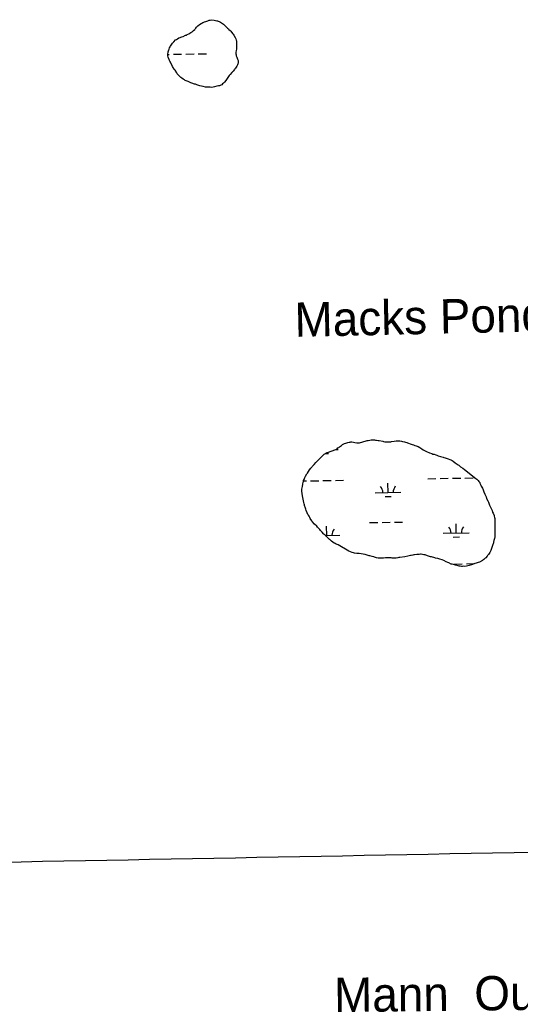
# Model space of a CAD drawing. Extents: x 3957609 to 3995875, y 234277 to 260273.
# Drawn here: x 3968015 to 3969955, y 248323 to 252171 of the extents above; entities that cross this region are included whole.
import ezdxf

# ---------------------------------------------------------------- set-up
doc = ezdxf.new("R2010")
doc.units = 0
for name, color, linetype in [('V-GRID-MAJR', 7, 'Continuous'), ('V-RIVR-IDEN', 7, 'Continuous'), ('V-TOPO-SHOR', 7, 'Continuous'), ('V-WETL-SWMP', 7, 'Continuous')]:
    doc.layers.add(name, color=color, linetype=linetype)

msp = doc.modelspace()

# ---------------------------------------------------------------- linework, layer by layer
at = {"layer": 'V-GRID-MAJR'}
msp.add_spline([(3961703.892, 248787.859), (3967022.571, 248887.277), (3972341.236, 248987.469), (3977659.886, 249088.434), (3982978.522, 249190.173), (3988297.143, 249292.685), (3993615.748, 249395.971), (3993615.749, 249395.971)], degree=3, dxfattribs=at)
at = {"layer": 'V-TOPO-SHOR'}
for points in [[(3968590.487, 252047.006), (3968591.671, 252050.578), (3968593.252, 252053.753), (3968594.438, 252056.927), (3968596.015, 252062.086), (3968597.596, 252065.658), (3968599.572, 252068.437), (3968603.922, 252075.977), (3968607.088, 252080.346), (3968609.464, 252082.728), (3968611.84, 252085.509), (3968618.967, 252092.656), (3968622.135, 252094.645), (3968626.096, 252097.426), (3968631.644, 252100.609), (3968636.397, 252102.599), (3968639.965, 252103.795), (3968643.137, 252104.592), (3968647.893, 252106.187), (3968657.801, 252110.564), (3968661.366, 252111.76), (3968664.535, 252114.146), (3968670.478, 252116.929), (3968678.008, 252120.909), (3968683.157, 252124.486), (3968685.928, 252127.266), (3968689.096, 252129.649), (3968693.055, 252133.623), (3968695.036, 252136.402), (3968697.409, 252138.786), (3968700.575, 252142.755), (3968702.951, 252144.741), (3968705.327, 252147.522), (3968711.663, 252152.687), (3968718.002, 252157.06), (3968720.777, 252158.254), (3968725.135, 252159.847), (3968727.908, 252161.834), (3968731.078, 252162.632), (3968736.231, 252164.623), (3968739.799, 252165.819), (3968743.764, 252166.62), (3968749.312, 252169.008), (3968752.482, 252169.805), (3968759.619, 252170.609), (3968768.344, 252169.831), (3968773.898, 252168.649), (3968778.659, 252167.07), (3968781.834, 252166.284), (3968784.611, 252165.098), (3968788.183, 252163.914), (3968792.944, 252161.543), (3968796.516, 252159.169), (3968800.487, 252156.003), (3968804.458, 252153.232), (3968806.842, 252150.858), (3968810.414, 252148.485), (3968820.344, 252138.587), (3968823.521, 252136.211), (3968825.905, 252133.44), (3968830.67, 252128.689), (3968833.45, 252126.313), (3968840.206, 252117.996), (3968842.193, 252114.828), (3968844.976, 252111.262), (3968849.75, 252101.754), (3968852.138, 252096.603), (3968853.731, 252091.845), (3968854.53, 252088.675), (3968855.73, 252081.54), (3968855.74, 252075.193), (3968855.353, 252070.038), (3968855.357, 252066.469), (3968854.573, 252061.312), (3968854.579, 252057.742), (3968853.399, 252050.603), (3968853.012, 252045.448), (3968853.022, 252039.103), (3968853.426, 252035.534), (3968854.227, 252030.776), (3968856.215, 252026.418), (3968859.005, 252018.49), (3968861.393, 252012.942), (3968862.191, 252009.374), (3968862.195, 252006.202), (3968861.806, 252002.632), (3968860.62, 251999.458), (3968859.039, 251995.886), (3968856.67, 251991.125), (3968851.525, 251983.185), (3968849.152, 251980.405), (3968847.173, 251977.626), (3968842.027, 251971.671), (3968836.88, 251966.108), (3968830.152, 251958.166), (3968826.986, 251954.197), (3968823.82, 251950.623), (3968821.842, 251947.447), (3968818.675, 251943.476), (3968814.325, 251935.935), (3968808.786, 251929.185)], [(3968808.786, 251929.185), (3968804.827, 251925.212), (3968801.261, 251922.033), (3968797.698, 251919.252), (3968794.132, 251916.866), (3968789.774, 251915.275), (3968785.014, 251914.472), (3968779.466, 251912.879), (3968769.556, 251910.483), (3968760.041, 251908.881), (3968753.299, 251909.266), (3968750.127, 251909.657), (3968744.575, 251909.254), (3968735.056, 251910.03), (3968725.536, 251911.601), (3968713.236, 251915.15), (3968709.666, 251915.939), (3968705.697, 251917.518), (3968701.333, 251918.699), (3968696.176, 251920.676), (3968692.605, 251921.462), (3968681.894, 251925.013), (3968678.717, 251926.594), (3968675.147, 251927.778), (3968667.209, 251930.938), (3968659.671, 251934.495), (3968656.496, 251935.679), (3968653.715, 251937.658), (3968648.556, 251940.426), (3968642.998, 251944.383), (3968639.424, 251947.152), (3968635.85, 251951.113), (3968631.482, 251954.674), (3968625.522, 251961.803), (3968623.534, 251964.576), (3968616.775, 251975.271), (3968613.597, 251979.629), (3968607.234, 251990.326), (3968605.247, 251993.099), (3968600.871, 252002.213), (3968598.88, 252006.968), (3968596.891, 252009.741), (3968595.697, 252012.911), (3968593.709, 252016.477), (3968592.515, 252019.252), (3968590.522, 252025.99), (3968588.529, 252031.538), (3968588.521, 252035.9), (3968590.487, 252047.006)], [(3969108.75, 250350.965), (3969110.714, 250361.279), (3969111.892, 250370.006), (3969113.464, 250377.542), (3969114.65, 250380.717), (3969115.439, 250383.889), (3969117.413, 250388.653), (3969118.597, 250392.222), (3969120.178, 250395.399), (3969122.152, 250400.556), (3969127.69, 250410.083), (3969130.064, 250413.259), (3969138.768, 250425.963), (3969143.515, 250432.316), (3969146.683, 250435.493), (3969148.659, 250439.066), (3969156.182, 250446.611), (3969162.911, 250454.158), (3969172.019, 250463.292), (3969173.997, 250465.676), (3969177.165, 250468.457), (3969191.022, 250482.359), (3969195.378, 250486.332), (3969206.075, 250492.298), (3969211.228, 250494.686), (3969222.721, 250498.274), (3969239.763, 250504.645), (3969244.913, 250507.429), (3969248.479, 250510.607), (3969251.647, 250512.198), (3969254.815, 250514.98), (3969261.944, 250520.147), (3969265.905, 250523.325), (3969268.678, 250525.314), (3969273.829, 250527.7), (3969278.584, 250529.69), (3969286.91, 250532.084), (3969292.46, 250533.283), (3969295.632, 250533.287), (3969298.804, 250533.688), (3969302.769, 250533.696), (3969308.321, 250533.307), (3969313.478, 250531.73), (3969321.412, 250530.95), (3969332.119, 250530.966), (3969344.805, 250533.764), (3969358.28, 250537.751), (3969361.453, 250538.945), (3969365.018, 250539.744), (3969372.156, 250540.549), (3969376.913, 250541.747), (3969382.068, 250542.15), (3969389.602, 250541.767), (3969393.967, 250540.981), (3969397.932, 250540.987), (3969404.676, 250539.412), (3969408.643, 250539.021), (3969422.526, 250536.269), (3969425.698, 250535.877), (3969430.857, 250534.696), (3969437.202, 250533.911), (3969444.737, 250533.924), (3969453.064, 250534.73), (3969456.631, 250535.529), (3969466.146, 250537.131), (3969473.681, 250537.54), (3969476.853, 250537.544), (3969481.611, 250537.95), (3969484.783, 250537.559), (3969488.353, 250537.565), (3969494.304, 250536.383), (3969498.269, 250535.994), (3969506.203, 250534.024), (3969510.965, 250532.445), (3969515.329, 250531.261), (3969518.106, 250530.077), (3969532.391, 250525.738), (3969535.963, 250524.159), (3969541.12, 250522.58), (3969543.899, 250521.394), (3969547.071, 250520.605), (3969552.23, 250518.236), (3969555.404, 250517.447), (3969558.976, 250515.866), (3969565.724, 250511.912), (3969569.296, 250510.333), (3969573.265, 250507.166), (3969579.221, 250503.607), (3969591.525, 250496.883), (3969603.035, 250491.352), (3969612.159, 250488.589), (3969616.525, 250487.01), (3969621.285, 250485.828), (3969627.633, 250483.461), (3969632.395, 250482.277), (3969636.759, 250480.303), (3969645.488, 250477.937), (3969651.439, 250475.568), (3969655.804, 250474.781), (3969659.373, 250473.598), (3969664.532, 250471.621)], [(3969664.532, 250471.621), (3969672.071, 250469.651), (3969676.038, 250468.072), (3969681.991, 250465.305), (3969685.561, 250464.519), (3969688.338, 250463.333), (3969691.515, 250461.752), (3969694.691, 250459.774), (3969703.028, 250453.046), (3969706.207, 250450.275), (3969710.176, 250447.901), (3969714.145, 250445.133), (3969716.924, 250443.551), (3969719.306, 250441.571), (3969721.292, 250439.593), (3969723.279, 250437.217), (3969733.202, 250431.679), (3969739.554, 250426.932), (3969783.629, 250391.708), (3969786.806, 250389.335), (3969791.572, 250384.981), (3969795.147, 250381.022), (3969797.929, 250377.059), (3969798.727, 250373.889), (3969800.319, 250371.116), (3969802.707, 250365.963), (3969804.3, 250362), (3969808.275, 250354.869), (3969811.062, 250348.528), (3969813.051, 250344.565), (3969814.247, 250340.603), (3969818.228, 250331.092), (3969822.607, 250321.581), (3969824.995, 250314.448), (3969828.976, 250305.332), (3969831.762, 250300.181), (3969836.538, 250288.69), (3969842.507, 250275.214), (3969846.487, 250267.688), (3969848.08, 250262.138), (3969850.468, 250258.177), (3969853.655, 250249.059), (3969854.453, 250245.491), (3969856.049, 250240.341), (3969856.845, 250237.168), (3969856.852, 250233.601), (3969857.253, 250230.031), (3969857.3, 250201.48), (3969856.913, 250195.53), (3969856.923, 250189.186), (3969856.536, 250183.632), (3969856.542, 250179.269), (3969856.944, 250176.097), (3969856.559, 250169.355), (3969856.565, 250166.185), (3969855.385, 250159.441), (3969854.202, 250155.076), (3969853.415, 250151.109), (3969851.443, 250145.553), (3969851.05, 250142.381), (3969847.498, 250132.065), (3969845.917, 250128.891), (3969844.734, 250124.526), (3969840.785, 250113.416), (3969836.834, 250104.685), (3969832.087, 250097.143), (3969828.921, 250093.569), (3969826.943, 250090.79), (3969821.798, 250084.834), (3969819.025, 250082.845), (3969813.481, 250077.68), (3969810.708, 250075.694), (3969808.332, 250073.707), (3969797.238, 250067.741), (3969792.086, 250065.751), (3969787.725, 250064.553), (3969784.952, 250063.359), (3969779.8, 250062.161), (3969775.835, 250060.965), (3969769.494, 250058.575), (3969765.927, 250057.778), (3969757.603, 250054.986), (3969746.503, 250052.193), (3969738.573, 250051.386), (3969733.814, 250051.775), (3969730.246, 250050.979), (3969727.074, 250050.972), (3969722.314, 250051.759), (3969718.745, 250052.545), (3969714.776, 250053.729), (3969704.067, 250055.693), (3969699.702, 250056.877), (3969690.974, 250060.035), (3969687.007, 250060.426), (3969677.879, 250064.774), (3969674.307, 250065.958), (3969667.956, 250069.515), (3969658.431, 250074.258), (3969652.48, 250076.63), (3969642.956, 250079.786), (3969636.212, 250081.758)], [(3969636.212, 250081.758), (3969627.089, 250083.726), (3969623.914, 250084.91), (3969620.344, 250085.301), (3969615.188, 250086.483), (3969611.219, 250088.062), (3969607.649, 250088.453), (3969598.92, 250091.216), (3969595.748, 250092.002), (3969586.223, 250095.557), (3969581.861, 250096.344), (3969575.909, 250097.919), (3969571.547, 250098.705), (3969567.975, 250098.699), (3969563.617, 250097.9), (3969557.667, 250097.89), (3969554.1, 250097.489), (3969545.775, 250095.492), (3969542.602, 250095.486), (3969538.242, 250094.29), (3969532.69, 250093.487), (3969529.52, 250093.483), (3969518.817, 250090.689), (3969507.319, 250088.291), (3969488.287, 250086.278), (3969484.72, 250085.479), (3969480.755, 250085.076), (3969473.62, 250083.083), (3969458.948, 250083.058), (3969454.188, 250083.843), (3969450.221, 250083.837), (3969447.049, 250084.625), (3969441.497, 250085.012), (3969433.168, 250085), (3969425.24, 250083.798), (3969421.273, 250083.79), (3969417.31, 250082.991), (3969412.153, 250082.983), (3969408.188, 250082.579), (3969403.826, 250082.968), (3969398.272, 250084.15), (3969393.907, 250085.729), (3969390.735, 250086.517), (3969387.956, 250087.701), (3969380.814, 250089.276), (3969372.483, 250091.644), (3969369.309, 250092.827), (3969365.739, 250093.616), (3969353.441, 250097.163), (3969337.968, 250099.915), (3969331.226, 250100.698), (3969326.862, 250101.482), (3969322.104, 250101.871), (3969312.583, 250103.047), (3969308.616, 250104.231), (3969303.064, 250105.015), (3969290.367, 250110.149), (3969249.083, 250135.065), (3969241.147, 250137.828), (3969237.973, 250139.806), (3969234.401, 250141.783), (3969223.68, 250149.301), (3969218.914, 250154.052), (3969216.135, 250156.031), (3969213.753, 250158.406), (3969206.603, 250164.344), (3969203.822, 250167.512), (3969198.661, 250171.864), (3969195.483, 250175.032), (3969192.306, 250177.803), (3969186.744, 250184.139), (3969181.182, 250190.871), (3969178.003, 250194.037), (3969172.043, 250201.167), (3969169.264, 250203.542), (3969166.88, 250206.711), (3969158.142, 250215.421), (3969149.003, 250225.718), (3969146.62, 250228.092), (3969140.658, 250237.203), (3969139.064, 250240.771), (3969136.281, 250246.317), (3969134.293, 250249.882), (3969132.304, 250252.655), (3969129.519, 250258.601), (3969125.539, 250267.714), (3969123.944, 250273.262), (3969122.351, 250277.225), (3969119.162, 250287.135), (3969118.363, 250290.308), (3969117.169, 250293.476), (3969115.574, 250299.026), (3969110.773, 250324.794), (3969109.966, 250334.311), (3969108.365, 250343.431), (3969108.359, 250346.999), (3969108.75, 250350.965)]]:
    msp.add_lwpolyline(points, dxfattribs=at)
at = {"layer": 'V-WETL-SWMP'}
for p, q in [((3968588.656, 252036.655), (3968594.454, 252036.761)), ((3968610.452, 252037.052), (3968642.446, 252037.633)), ((3968658.444, 252037.924), (3968690.438, 252038.506)), ((3968706.436, 252038.797), (3968738.431, 252039.379)), ((3969240.319, 250504.945), (3969249.16, 250505.106)), ((3969199.758, 250488.774), (3969211.447, 250488.987)), ((3969115.112, 250382.578), (3969126.52, 250382.785)), ((3969142.517, 250383.076), (3969174.512, 250383.658)), ((3969190.509, 250383.949), (3969222.504, 250384.531)), ((3969238.501, 250384.822), (3969270.496, 250385.403)), ((3969596.35, 250391.328), (3969628.345, 250391.91)), ((3969644.342, 250392.201), (3969676.337, 250392.783)), ((3969692.334, 250393.074), (3969724.329, 250393.655)), ((3969740.326, 250393.946), (3969772.321, 250394.528)), ((3969442.706, 250337.784), (3969442.052, 250373.778)), ((3969392.714, 250336.875), (3969492.698, 250338.693)), ((3969430.989, 250322.138), (3969454.985, 250322.574)), ((3969205.216, 250171.577), (3969204.562, 250207.571)), ((3969371.409, 250221.037), (3969403.403, 250221.619)), ((3969419.401, 250221.909), (3969451.396, 250222.491)), ((3969467.393, 250222.782), (3969499.388, 250223.364)), ((3969707.042, 250180.702), (3969706.387, 250216.696)), ((3969199.132, 250171.467), (3969255.208, 250172.486)), ((3969215.827, 250156.337), (3969217.495, 250156.367)), ((3969657.05, 250179.793), (3969757.033, 250181.611)), ((3969695.324, 250165.055), (3969719.32, 250165.492)), ((3969698.382, 250060.454), (3969730.377, 250061.035)), ((3969746.374, 250061.326), (3969778.369, 250061.908))]:
    msp.add_line(p, q, dxfattribs=at)
for points in [[(3968590.487, 252047.007), (3968591.671, 252050.578), (3968593.252, 252053.753), (3968594.437, 252056.927), (3968596.015, 252062.085), (3968597.595, 252065.657), (3968599.573, 252068.436), (3968603.923, 252075.977), (3968607.089, 252080.345), (3968609.464, 252082.728), (3968611.839, 252085.508), (3968618.966, 252092.657), (3968622.135, 252094.645), (3968626.096, 252097.427), (3968631.643, 252100.609), (3968636.398, 252102.599), (3968639.965, 252103.795), (3968643.137, 252104.593), (3968647.893, 252106.187), (3968657.8, 252110.565), (3968661.367, 252111.76), (3968664.535, 252114.145), (3968670.479, 252116.93), (3968678.008, 252120.908), (3968683.157, 252124.486), (3968685.929, 252127.266), (3968689.097, 252129.65), (3968693.056, 252133.622), (3968695.035, 252136.401), (3968697.41, 252138.785), (3968700.576, 252142.755), (3968702.952, 252144.742), (3968705.327, 252147.522), (3968711.664, 252152.687), (3968718.002, 252157.06), (3968720.776, 252158.254), (3968725.135, 252159.847), (3968727.908, 252161.834), (3968731.079, 252162.633), (3968736.231, 252164.624), (3968739.799, 252165.819), (3968743.763, 252166.619), (3968749.311, 252169.007), (3968752.482, 252169.805), (3968759.619, 252170.61), (3968768.344, 252169.831), (3968773.898, 252168.65), (3968778.659, 252167.071), (3968781.833, 252166.283), (3968784.611, 252165.098), (3968788.182, 252163.914), (3968792.944, 252161.543), (3968796.517, 252159.169), (3968800.488, 252156.003), (3968804.458, 252153.233), (3968806.841, 252150.858), (3968810.414, 252148.484), (3968820.344, 252138.586), (3968823.52, 252136.212), (3968825.904, 252133.44), (3968830.671, 252128.689), (3968833.45, 252126.314), (3968840.205, 252117.997), (3968842.193, 252114.828), (3968844.975, 252111.263), (3968849.749, 252101.754), (3968852.137, 252096.602), (3968853.73, 252091.846), (3968854.529, 252088.675), (3968855.73, 252081.539), (3968855.74, 252075.194), (3968855.352, 252070.038), (3968855.358, 252066.469), (3968854.573, 252061.312), (3968854.579, 252057.743), (3968853.4, 252050.603), (3968853.012, 252045.447), (3968853.022, 252039.103), (3968853.425, 252035.534), (3968854.226, 252030.777), (3968856.215, 252026.418), (3968859.004, 252018.491), (3968861.392, 252012.943), (3968862.191, 252009.375), (3968862.196, 252006.203), (3968861.806, 252002.633), (3968860.621, 251999.459), (3968859.04, 251995.887), (3968856.669, 251991.125), (3968851.526, 251983.185), (3968849.151, 251980.405), (3968847.173, 251977.626), (3968842.027, 251971.67), (3968836.881, 251966.109), (3968830.152, 251958.167), (3968826.986, 251954.197), (3968823.82, 251950.623), (3968821.842, 251947.447), (3968818.676, 251943.476), (3968814.326, 251935.935), (3968808.785, 251929.184)], [(3968808.785, 251929.184), (3968804.826, 251925.212), (3968801.262, 251922.034), (3968797.697, 251919.252), (3968794.132, 251916.867), (3968789.773, 251915.274), (3968785.015, 251914.473), (3968779.466, 251912.878), (3968769.556, 251910.483), (3968760.041, 251908.881), (3968753.299, 251909.267), (3968750.126, 251909.658), (3968744.574, 251909.253), (3968735.056, 251910.03), (3968725.536, 251911.601), (3968713.237, 251915.15), (3968709.666, 251915.938), (3968705.698, 251917.518), (3968701.334, 251918.7), (3968696.176, 251920.675), (3968692.605, 251921.462), (3968681.893, 251925.014), (3968678.718, 251926.595), (3968675.147, 251927.779), (3968667.21, 251930.939), (3968659.67, 251934.496), (3968656.496, 251935.68), (3968653.716, 251937.658), (3968648.557, 251940.426), (3968642.998, 251944.383), (3968639.425, 251947.153), (3968635.85, 251951.113), (3968631.482, 251954.675), (3968625.522, 251961.803), (3968623.534, 251964.576), (3968616.776, 251975.272), (3968613.596, 251979.629), (3968607.234, 251990.326), (3968605.247, 251993.099), (3968600.87, 252002.212), (3968598.879, 252006.968), (3968596.892, 252009.741), (3968595.697, 252012.911), (3968593.709, 252016.477), (3968592.515, 252019.251), (3968590.521, 252025.989), (3968588.529, 252031.538), (3968588.522, 252035.9), (3968590.487, 252047.007)], [(3969114.65, 250380.716), (3969115.438, 250383.89), (3969117.413, 250388.652), (3969118.597, 250392.223), (3969120.178, 250395.398), (3969122.152, 250400.556), (3969127.689, 250410.083), (3969130.063, 250413.259), (3969138.767, 250425.963), (3969143.515, 250432.316), (3969146.683, 250435.493), (3969148.66, 250439.066), (3969156.182, 250446.612), (3969162.912, 250454.158), (3969172.018, 250463.293), (3969173.997, 250465.676), (3969177.165, 250468.457), (3969191.022, 250482.359), (3969195.378, 250486.332), (3969206.075, 250492.297), (3969211.227, 250494.685), (3969222.721, 250498.273), (3969239.763, 250504.645), (3969244.914, 250507.429), (3969248.478, 250510.607), (3969251.647, 250512.199), (3969254.815, 250514.98), (3969261.945, 250520.147), (3969265.906, 250523.326), (3969268.678, 250525.313), (3969273.83, 250527.7), (3969278.585, 250529.691), (3969286.909, 250532.084), (3969292.459, 250533.282), (3969295.632, 250533.287), (3969298.804, 250533.689), (3969302.769, 250533.696), (3969308.322, 250533.308), (3969313.479, 250531.73), (3969321.412, 250530.95), (3969332.119, 250530.967), (3969344.804, 250533.763), (3969358.281, 250537.751), (3969361.452, 250538.945), (3969365.019, 250539.744), (3969372.156, 250540.549), (3969376.913, 250541.746), (3969382.068, 250542.151), (3969389.603, 250541.767), (3969393.966, 250540.981), (3969397.932, 250540.987), (3969404.676, 250539.412), (3969408.642, 250539.022), (3969422.526, 250536.268), (3969425.699, 250535.877), (3969430.857, 250534.695), (3969437.203, 250533.912), (3969444.737, 250533.924), (3969453.064, 250534.731), (3969456.632, 250535.53), (3969466.147, 250537.131), (3969473.681, 250537.54), (3969476.853, 250537.545), (3969481.611, 250537.95), (3969484.784, 250537.558), (3969488.353, 250537.564), (3969494.304, 250536.384), (3969498.27, 250535.994), (3969506.204, 250534.024), (3969510.965, 250532.445), (3969515.33, 250531.262), (3969518.107, 250530.077), (3969532.391, 250525.738), (3969535.962, 250524.158), (3969541.12, 250522.58), (3969543.898, 250521.394), (3969547.072, 250520.606), (3969552.231, 250518.235), (3969555.404, 250517.447), (3969558.976, 250515.867), (3969565.724, 250511.912), (3969569.296, 250510.332), (3969573.266, 250507.166), (3969579.22, 250503.606), (3969591.525, 250496.884), (3969603.034, 250491.351), (3969612.159, 250488.59), (3969616.524, 250487.011), (3969621.284, 250485.829), (3969627.633, 250483.46), (3969632.394, 250482.278), (3969636.759, 250480.302), (3969645.487, 250477.937), (3969651.44, 250475.567), (3969655.803, 250474.781), (3969659.374, 250473.597), (3969664.532, 250471.622), (3969672.07, 250469.652), (3969676.038, 250468.072), (3969681.991, 250465.306), (3969685.562, 250464.518)], [(3969685.562, 250464.518), (3969688.339, 250463.333), (3969691.515, 250461.752), (3969694.69, 250459.774), (3969703.029, 250453.046), (3969706.206, 250450.275), (3969710.175, 250447.902), (3969714.145, 250445.133), (3969716.924, 250443.551), (3969719.306, 250441.572), (3969721.292, 250439.592), (3969723.279, 250437.216), (3969733.202, 250431.68), (3969739.555, 250426.932), (3969783.63, 250391.709), (3969786.806, 250389.335), (3969791.572, 250384.98), (3969795.147, 250381.021), (3969797.929, 250377.059), (3969798.728, 250373.888), (3969800.318, 250371.115), (3969802.706, 250365.963), (3969804.299, 250362), (3969808.276, 250354.869), (3969811.062, 250348.528), (3969813.051, 250344.566), (3969814.247, 250340.602), (3969818.228, 250331.091), (3969822.606, 250321.581), (3969824.996, 250314.447), (3969828.977, 250305.332), (3969831.761, 250300.181), (3969836.538, 250288.689), (3969842.508, 250275.215), (3969846.486, 250267.687), (3969848.081, 250262.138), (3969850.467, 250258.176), (3969853.654, 250249.06), (3969854.453, 250245.492), (3969856.048, 250240.34), (3969856.846, 250237.169), (3969856.852, 250233.6), (3969857.254, 250230.031), (3969857.3, 250201.479), (3969856.913, 250195.53), (3969856.923, 250189.185), (3969856.536, 250183.632), (3969856.543, 250179.27), (3969856.944, 250176.098), (3969856.559, 250169.356), (3969856.564, 250166.184), (3969855.385, 250159.44), (3969854.202, 250155.076), (3969853.416, 250151.109), (3969851.442, 250145.554), (3969851.05, 250142.381), (3969847.498, 250132.065), (3969845.917, 250128.89), (3969844.734, 250124.526), (3969840.786, 250113.416), (3969836.835, 250104.685), (3969832.088, 250097.143), (3969828.922, 250093.569), (3969826.943, 250090.789), (3969821.798, 250084.833), (3969819.025, 250082.846), (3969813.481, 250077.681), (3969810.709, 250075.694), (3969808.333, 250073.707), (3969797.238, 250067.741), (3969792.086, 250065.75), (3969787.726, 250064.553), (3969784.952, 250063.359), (3969779.799, 250062.161), (3969775.835, 250060.965), (3969769.494, 250058.575), (3969765.926, 250057.777), (3969757.603, 250054.987), (3969746.504, 250052.193), (3969738.574, 250051.387), (3969733.814, 250051.776), (3969730.247, 250050.978), (3969727.074, 250050.972), (3969722.314, 250051.758), (3969718.744, 250052.545), (3969714.776, 250053.728), (3969704.066, 250055.694), (3969699.702, 250056.877), (3969690.973, 250060.035), (3969687.006, 250060.425), (3969677.878, 250064.773), (3969674.308, 250065.957), (3969667.957, 250069.515), (3969658.432, 250074.259), (3969652.479, 250076.629), (3969642.957, 250079.786), (3969636.212, 250081.758)], [(3969636.212, 250081.758), (3969627.088, 250083.726), (3969623.914, 250084.91), (3969620.344, 250085.301), (3969615.187, 250086.482), (3969611.219, 250088.062), (3969607.649, 250088.453), (3969598.92, 250091.215), (3969595.747, 250092.003), (3969586.223, 250095.557), (3969581.86, 250096.343), (3969575.909, 250097.919), (3969571.546, 250098.705), (3969567.976, 250098.7), (3969563.616, 250097.9), (3969557.667, 250097.89), (3969554.099, 250097.488), (3969545.774, 250095.491), (3969542.602, 250095.486), (3969538.242, 250094.29), (3969532.691, 250093.487), (3969529.519, 250093.482), (3969518.816, 250090.689), (3969507.32, 250088.291), (3969488.288, 250086.278), (3969484.72, 250085.479), (3969480.755, 250085.076), (3969473.62, 250083.082), (3969458.948, 250083.058), (3969454.188, 250083.843), (3969450.222, 250083.837), (3969447.048, 250084.625), (3969441.496, 250085.013), (3969433.168, 250084.999), (3969425.239, 250083.797), (3969421.273, 250083.79), (3969417.309, 250082.991), (3969412.154, 250082.983), (3969408.189, 250082.58), (3969403.826, 250082.969), (3969398.272, 250084.15), (3969393.907, 250085.729), (3969390.734, 250086.517), (3969387.956, 250087.702), (3969380.815, 250089.277), (3969372.483, 250091.643), (3969369.309, 250092.827), (3969365.739, 250093.615), (3969353.44, 250097.164), (3969337.969, 250099.915), (3969331.227, 250100.697), (3969326.863, 250101.483), (3969322.104, 250101.872), (3969312.584, 250103.047), (3969308.617, 250104.23), (3969303.064, 250105.014), (3969290.366, 250110.149), (3969249.083, 250135.066), (3969241.147, 250137.829), (3969237.972, 250139.806), (3969234.4, 250141.783), (3969223.68, 250149.301), (3969218.914, 250154.052), (3969216.135, 250156.03), (3969213.752, 250158.406), (3969206.604, 250164.343), (3969203.823, 250167.511), (3969198.661, 250171.864), (3969195.483, 250175.032), (3969192.306, 250177.803), (3969186.744, 250184.139), (3969181.181, 250190.871), (3969178.004, 250194.038), (3969172.044, 250201.167), (3969169.264, 250203.542), (3969166.88, 250206.71), (3969158.141, 250215.421), (3969149.004, 250225.717), (3969146.62, 250228.092), (3969140.657, 250237.203), (3969139.065, 250240.77), (3969136.281, 250246.317), (3969134.292, 250249.883), (3969132.305, 250252.656), (3969129.519, 250258.6), (3969125.539, 250267.714), (3969123.944, 250273.263), (3969122.351, 250277.226), (3969119.163, 250287.135), (3969118.364, 250290.307), (3969117.17, 250293.477), (3969115.574, 250299.026), (3969110.774, 250324.795), (3969109.966, 250334.311), (3969108.365, 250343.43), (3969108.359, 250346.999), (3969108.749, 250350.965), (3969110.715, 250361.279), (3969111.891, 250370.005), (3969113.465, 250377.542), (3969114.65, 250380.716)]]:
    msp.add_lwpolyline(points, dxfattribs=at)
for centre, start, end in [((3969387.464, 250337.255), 0.269879, 41.813537), ((3969497.931, 250339.263), 140.269876, 181.813534), ((3969260.442, 250173.056), 140.269876, 181.813534), ((3969651.799, 250180.172), 0.269879, 41.813537), ((3969762.267, 250182.181), 140.269876, 181.813534)]:
    msp.add_arc(centre, 35.246, start, end, dxfattribs=at)

# ---------------------------------------------------------------- texts
at = {"layer": 'V-RIVR-IDEN'}
for s, height, rotation, p in [('Macks Pond', 132.9997, 1.306889, (3969081.591, 250941.047)), ('Mann  Outside  Pond ', 132.99974, 0.658314, (3969234.145, 248322.683))]:
    msp.add_text(s, height=height, rotation=rotation, dxfattribs=at).set_placement(p)

doc.saveas('drawing.dxf')
